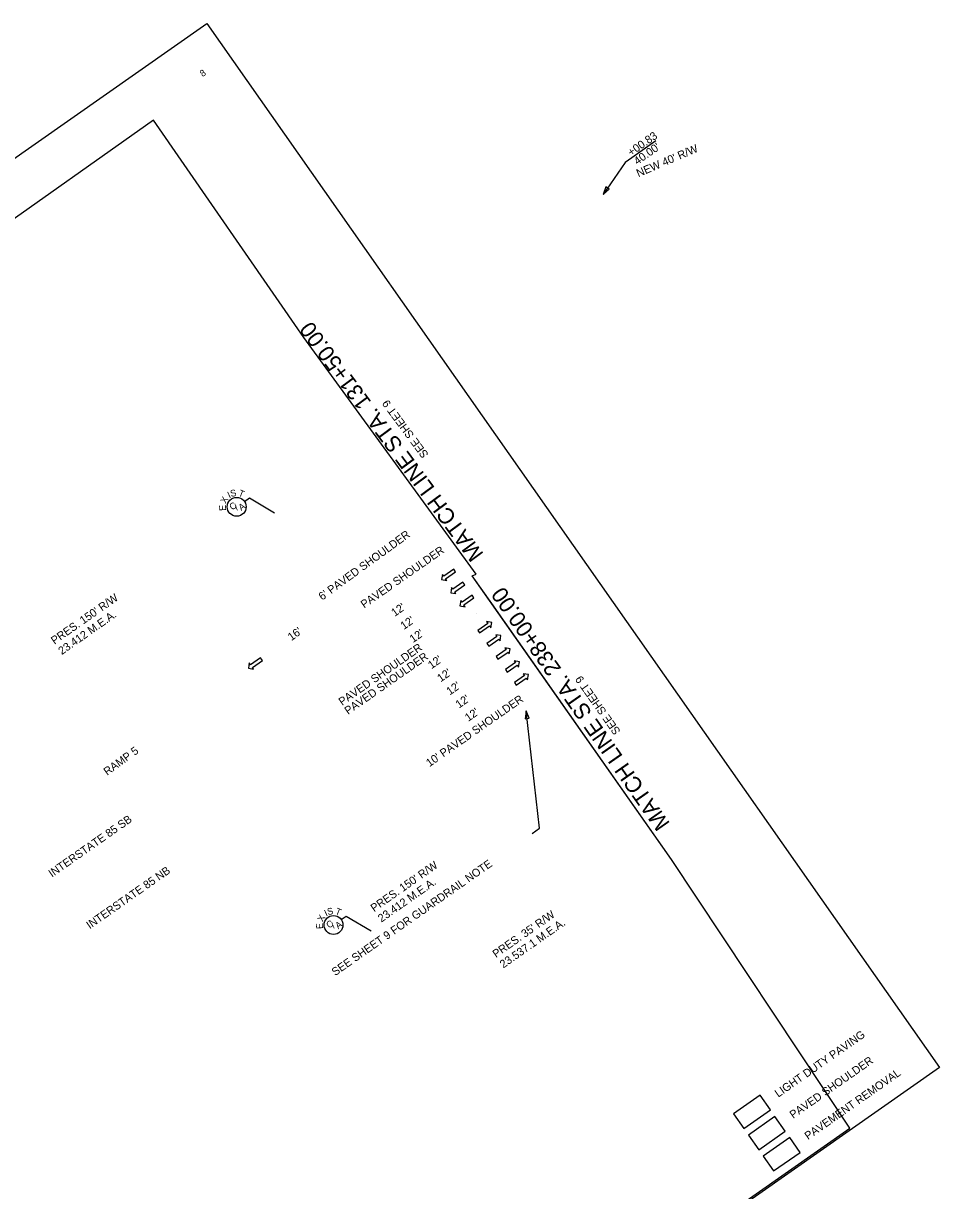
# Model space of a CAD drawing. Extents: x 1604963 to 1606883, y 1089540 to 1091304.
# Drawn here: x 1606197 to 1606883, y 1090409 to 1091285 of the extents above; entities that cross this region are included whole.
import ezdxf

# ---------------------------------------------------------------- set-up
doc = ezdxf.new("R2010")
doc.units = 0
for name, color, linetype in [('RD_DTM_BkLn1', 7, 'Continuous'), ('RD_DTM_Obscure', 7, 'Continuous'), ('RD_EX_Bldg', 7, 'Continuous'), ('RD_EX_BldgApp', 7, 'Continuous'), ('RD_EX_BldgChurch', 7, 'Continuous'), ('RD_EX_Fence_ChLk', 7, 'Continuous'), ('RD_EX_Fence_Other', 7, 'Continuous'), ('RD_EX_H2O_WetLd', 7, 'Continuous'), ('RD_EX_Misc', 7, 'Continuous'), ('RD_EX_Misc_Golf_Teebox', 7, 'Continuous'), ('RD_EX_UT', 7, 'Continuous'), ('RD_EX_VEG', 7, 'Continuous')]:
    doc.layers.add(name, color=color, linetype=linetype)

msp = doc.modelspace()

# ---------------------------------------------------------------- linework, layer by layer
at = {"layer": 'RD_DTM_Obscure'}
for p, q in [((1606362.25, 1090926.3), (1606365.99, 1090928.93)), ((1606365.99, 1090928.93), (1606384.77, 1090917.75)), ((1606434.85, 1090612.69), (1606438.6, 1090615.32)), ((1606438.6, 1090615.32), (1606457.37, 1090604.13))]:
    msp.add_line(p, q, dxfattribs=at)
for centre in [(1606356.45, 1090922.23), (1606429.05, 1090608.62)]:
    msp.add_circle(centre, 7.08, dxfattribs=at)
at = {"layer": 'RD_EX_Bldg'}
msp.add_lwpolyline([(1604962.76, 1090322.97), (1606334.05, 1091284.83), (1606883.32, 1090501.76), (1605512.03, 1089539.9)], close=True, dxfattribs=at)
at = {"layer": 'RD_EX_Fence_ChLk'}
msp.add_line((1606670.51, 1091196.62), (1606652.65, 1091184.08), dxfattribs=at)
msp.add_lwpolyline([(1606652.65, 1091184.08), (1606647.59, 1091180.54), (1606631.2, 1091156.48)], dxfattribs=at)
msp.add_lwpolyline([(1606633.18, 1091162.15), (1606631.2, 1091156.48), (1606635.75, 1091160.4)], close=True, dxfattribs=at)
at = {"layer": 'RD_EX_Fence_Other'}
msp.add_lwpolyline([(1604962.76, 1090322.97), (1606334.05, 1091284.83), (1606883.32, 1090501.76), (1605512.03, 1089539.9)], close=True, dxfattribs=at)
at = {"layer": 'RD_EX_H2O_WetLd'}
msp.add_lwpolyline([(1606575.7, 1090763.6), (1606573.5, 1090769.18), (1606572.61, 1090763.24)], close=True, dxfattribs=at)
msp.add_lwpolyline([(1606577.83, 1090677.32), (1606583.54, 1090681.33), (1606573.5, 1090769.18)], dxfattribs=at)
at = {"layer": 'RD_EX_Misc'}
for points in [[(1606520.49, 1090873.55), (1606519.11, 1090875.52), (1606511.6, 1090870.25), (1606510.67, 1090871.58), (1606509.97, 1090867.64), (1606513.91, 1090866.95), (1606512.98, 1090868.28)], [(1606527.38, 1090863.73), (1606526, 1090865.69), (1606518.49, 1090860.42), (1606517.56, 1090861.76), (1606516.86, 1090857.82), (1606520.8, 1090857.13), (1606519.87, 1090858.46)], [(1606534.27, 1090853.9), (1606532.89, 1090855.87), (1606525.38, 1090850.6), (1606524.45, 1090851.93), (1606523.76, 1090847.99), (1606527.7, 1090847.3), (1606526.76, 1090848.63)], [(1606537.16, 1090829.57), (1606538.53, 1090827.6), (1606546.04, 1090832.87), (1606546.98, 1090831.54), (1606547.67, 1090835.48), (1606543.73, 1090836.17), (1606544.66, 1090834.84)], [(1606544.05, 1090819.74), (1606545.42, 1090817.78), (1606552.93, 1090823.05), (1606553.87, 1090821.71), (1606554.56, 1090825.65), (1606550.62, 1090826.34), (1606551.55, 1090825.01)], [(1606550.94, 1090809.92), (1606552.31, 1090807.96), (1606559.82, 1090813.22), (1606560.76, 1090811.89), (1606561.45, 1090815.83), (1606557.51, 1090816.52), (1606558.45, 1090815.19)], [(1606375.71, 1090807.08), (1606374.33, 1090809.05), (1606366.83, 1090803.78), (1606365.89, 1090805.11), (1606365.2, 1090801.17), (1606369.14, 1090800.48), (1606368.2, 1090801.82)], [(1606557.83, 1090800.1), (1606559.2, 1090798.13), (1606566.71, 1090803.4), (1606567.65, 1090802.06), (1606568.34, 1090806), (1606564.4, 1090806.7), (1606565.34, 1090805.36)], [(1606564.59, 1090790.45), (1606565.97, 1090788.48), (1606573.48, 1090793.75), (1606574.42, 1090792.42), (1606575.11, 1090796.36), (1606571.17, 1090797.05), (1606572.1, 1090795.71)]]:
    msp.add_lwpolyline(points, close=True, dxfattribs=at)
at = {"layer": 'RD_EX_Misc_Golf_Teebox'}
msp.add_line((1606536.37, 1090842.18), (1606536.37, 1090842.18), dxfattribs=at)
for points in [[(1606736.57, 1090455.98), (1606756.44, 1090469.92), (1606748.72, 1090480.93), (1606728.85, 1090466.99)], [(1606747.73, 1090440.07), (1606767.6, 1090454.01), (1606759.88, 1090465.02), (1606740.01, 1090451.08)], [(1606758.89, 1090424.16), (1606778.76, 1090438.1), (1606771.03, 1090449.11), (1606751.17, 1090435.17)]]:
    msp.add_lwpolyline(points, close=True, dxfattribs=at)
for points in [[(1606736.57, 1090455.98), (1606756.44, 1090469.92), (1606748.72, 1090480.93), (1606728.85, 1090466.99), (1606736.57, 1090455.98)], [(1606747.73, 1090440.07), (1606767.6, 1090454.01), (1606759.88, 1090465.02), (1606740.01, 1090451.08), (1606747.73, 1090440.07)], [(1606758.89, 1090424.16), (1606778.76, 1090438.1), (1606771.03, 1090449.11), (1606751.17, 1090435.17), (1606758.89, 1090424.16)]]:
    msp.add_lwpolyline(points, dxfattribs=at)
at = {"layer": 'RD_EX_UT'}
msp.add_lwpolyline([(1605233.56, 1090111.04), (1605405.83, 1089865.44), (1605593.12, 1089598.42), (1606815.94, 1090456.14), (1606682.28, 1090657.78), (1606533.03, 1090870.55), (1606535.89, 1090871.82), (1606406.67, 1091049.1), (1606294.17, 1091212.27), (1606168.16, 1091123.23), (1606148, 1091151.76), (1605049.41, 1090375.46)], close=True, dxfattribs=at)
msp.add_lwpolyline([(1605233.56, 1090111.04), (1605405.83, 1089865.44), (1605593.12, 1089598.42), (1606815.94, 1090456.14), (1606682.28, 1090657.78), (1606533.03, 1090870.55), (1606535.89, 1090871.82), (1606406.67, 1091049.1), (1606294.17, 1091212.27), (1606168.16, 1091123.23), (1606148, 1091151.76), (1605049.41, 1090375.46)], close=True, dxfattribs=at)
at = {"layer": 'RD_EX_VEG'}
msp.add_line((1606535.89, 1090871.82), (1606406.67, 1091049.1), dxfattribs=at)
msp.add_lwpolyline([(1606682.28, 1090657.78), (1606547.72, 1090849.61), (1606533.03, 1090870.55)], dxfattribs=at)

# ---------------------------------------------------------------- texts
at = {"layer": 'RD_DTM_BkLn1'}
for s, p in [('INTERSTATE 85 SB', (1606218.02, 1090644.1)), ('INTERSTATE 85 NB', (1606246.36, 1090605.35))]:
    msp.add_text(s, height=6, rotation=35.05352, dxfattribs=at).set_placement(p)
at = {"layer": 'RD_DTM_Obscure'}
for s, rotation, p in [('X', 60.14035, (1606348.26, 1090924.21)), ('I', 24.97888, (1606350.89, 1090928.56)), ('S', 13.25838, (1606352.29, 1090929.56)), ('T', 338.09691, (1606357.27, 1090930.61)), ('E', 93.62747, (1606348.53, 1090919.36)), ('C', 35.04357, (1606353.1, 1090919.41)), ('/', 35.04357, (1606356.74, 1090919.39)), ('A', 35.04357, (1606359.88, 1090918.97)), ('S', 13.25838, (1606424.9, 1090615.95)), ('T', 338.09691, (1606429.88, 1090617)), ('X', 60.14035, (1606420.87, 1090610.59)), ('I', 24.97888, (1606423.5, 1090614.95)), ('C', 35.04357, (1606425.71, 1090605.8)), ('E', 93.62747, (1606421.13, 1090605.75)), ('/', 35.04357, (1606429.34, 1090605.77)), ('A', 35.04357, (1606432.49, 1090605.35))]:
    msp.add_text(s, height=5, rotation=rotation, dxfattribs=at).set_placement(p)
at = {"layer": 'RD_EX_BldgApp'}
for s, p in [("PRES. 150' R/W", (1606219.91, 1090818.75)), ('23.412 M.E.A.', (1606225.37, 1090810.97)), ("PRES. 150' R/W", (1606459.45, 1090618.12)), ('23.412 M.E.A.', (1606464.91, 1090610.35)), ("PRES. 35' R/W", (1606550.83, 1090583.72)), ('23.537.1 M.E.A.', (1606556.28, 1090575.94))]:
    msp.add_text(s, height=6, rotation=35.04683, dxfattribs=at).set_placement(p)
at = {"layer": 'RD_EX_BldgChurch'}
msp.add_text("NEW 40' R/W", height=6, rotation=23.25145, dxfattribs=at).set_placement((1606657.57, 1091169.34))
at = {"layer": 'RD_EX_Fence_ChLk'}
for s, p in [('+00.83', (1606652.11, 1091184.93)), ("40.00'", (1606656.71, 1091178.38))]:
    msp.add_text(s, height=6, rotation=35.04683, dxfattribs=at).set_placement(p)
at = {"layer": 'RD_EX_H2O_WetLd'}
msp.add_text('SEE SHEET 9 FOR GUARDRAIL NOTE', height=6, rotation=35.04683, dxfattribs=at).set_placement((1606430.3, 1090570.17))
at = {"layer": 'RD_EX_Misc_Golf_Teebox'}
for s, height, rotation, p in [('8', 5, 35.04683, (1606330.93, 1091244.46)), ("6' PAVED SHOULDER", 6, 36.08708, (1606420.56, 1090851.8)), ('PAVED SHOULDER', 6, 35.04683, (1606452.04, 1090845.87)), ("12'", 6, 35.04357, (1606474.88, 1090839.63)), ("12'", 6, 35.04357, (1606481.77, 1090829.8)), ("16'", 6, 36.06376, (1606397.45, 1090821.42)), ("12'", 6, 35.04357, (1606488.66, 1090819.98)), ('PAVED SHOULDER', 6, 35.0452, (1606435.51, 1090772.89)), ('PAVED SHOULDER', 6, 35.0452, (1606439.94, 1090766.11)), ("12'", 6, 35.04357, (1606502.44, 1090800.33)), ("12'", 6, 35.04357, (1606509.33, 1090790.51)), ("12'", 6, 35.04357, (1606516.22, 1090780.68)), ("10' PAVED SHOULDER", 6, 35.0452, (1606500.97, 1090726.94)), ("12'", 6, 35.04357, (1606523.11, 1090770.86)), ("12'", 6, 35.04357, (1606530.08, 1090760.93)), ('RAMP 5', 6, 36.06376, (1606259.4, 1090720.46)), ('LIGHT DUTY PAVING', 6, 35.04683, (1606762.36, 1090479.04)), ('PAVED SHOULDER', 6, 35.04683, (1606773.52, 1090463.13)), ('PAVEMENT REMOVAL', 6, 35.04683, (1606784.68, 1090447.22))]:
    msp.add_text(s, height=height, rotation=rotation, dxfattribs=at).set_placement(p)
at = {"layer": 'RD_EX_VEG'}
for s, height, rotation, p in [('MATCH LINE STA. 131+50.00', 12, 126.43589, (1606541.97, 1090886.83)), ('SEE SHEET 9', 6, 126.48715, (1606500.59, 1090961.54)), ('MATCH LINE STA. 238+00.00', 12, 125.04683, (1606681.6, 1090684.74)), ('SEE SHEET 9', 6, 125.0981, (1606644.42, 1090753.89))]:
    msp.add_text(s, height=height, rotation=rotation, dxfattribs=at).set_placement(p)

doc.saveas('drawing.dxf')
